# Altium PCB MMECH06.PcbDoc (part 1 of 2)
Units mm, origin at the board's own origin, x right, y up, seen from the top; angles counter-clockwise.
Board outline 65 x 56.01 mm, 4 copper layers (Top Layer, Ground Plane, Mid Layer 1, Bottom Layer), stack 1.442 mm thick; 107 components, 79 nets, 362 pads, 608 vias.
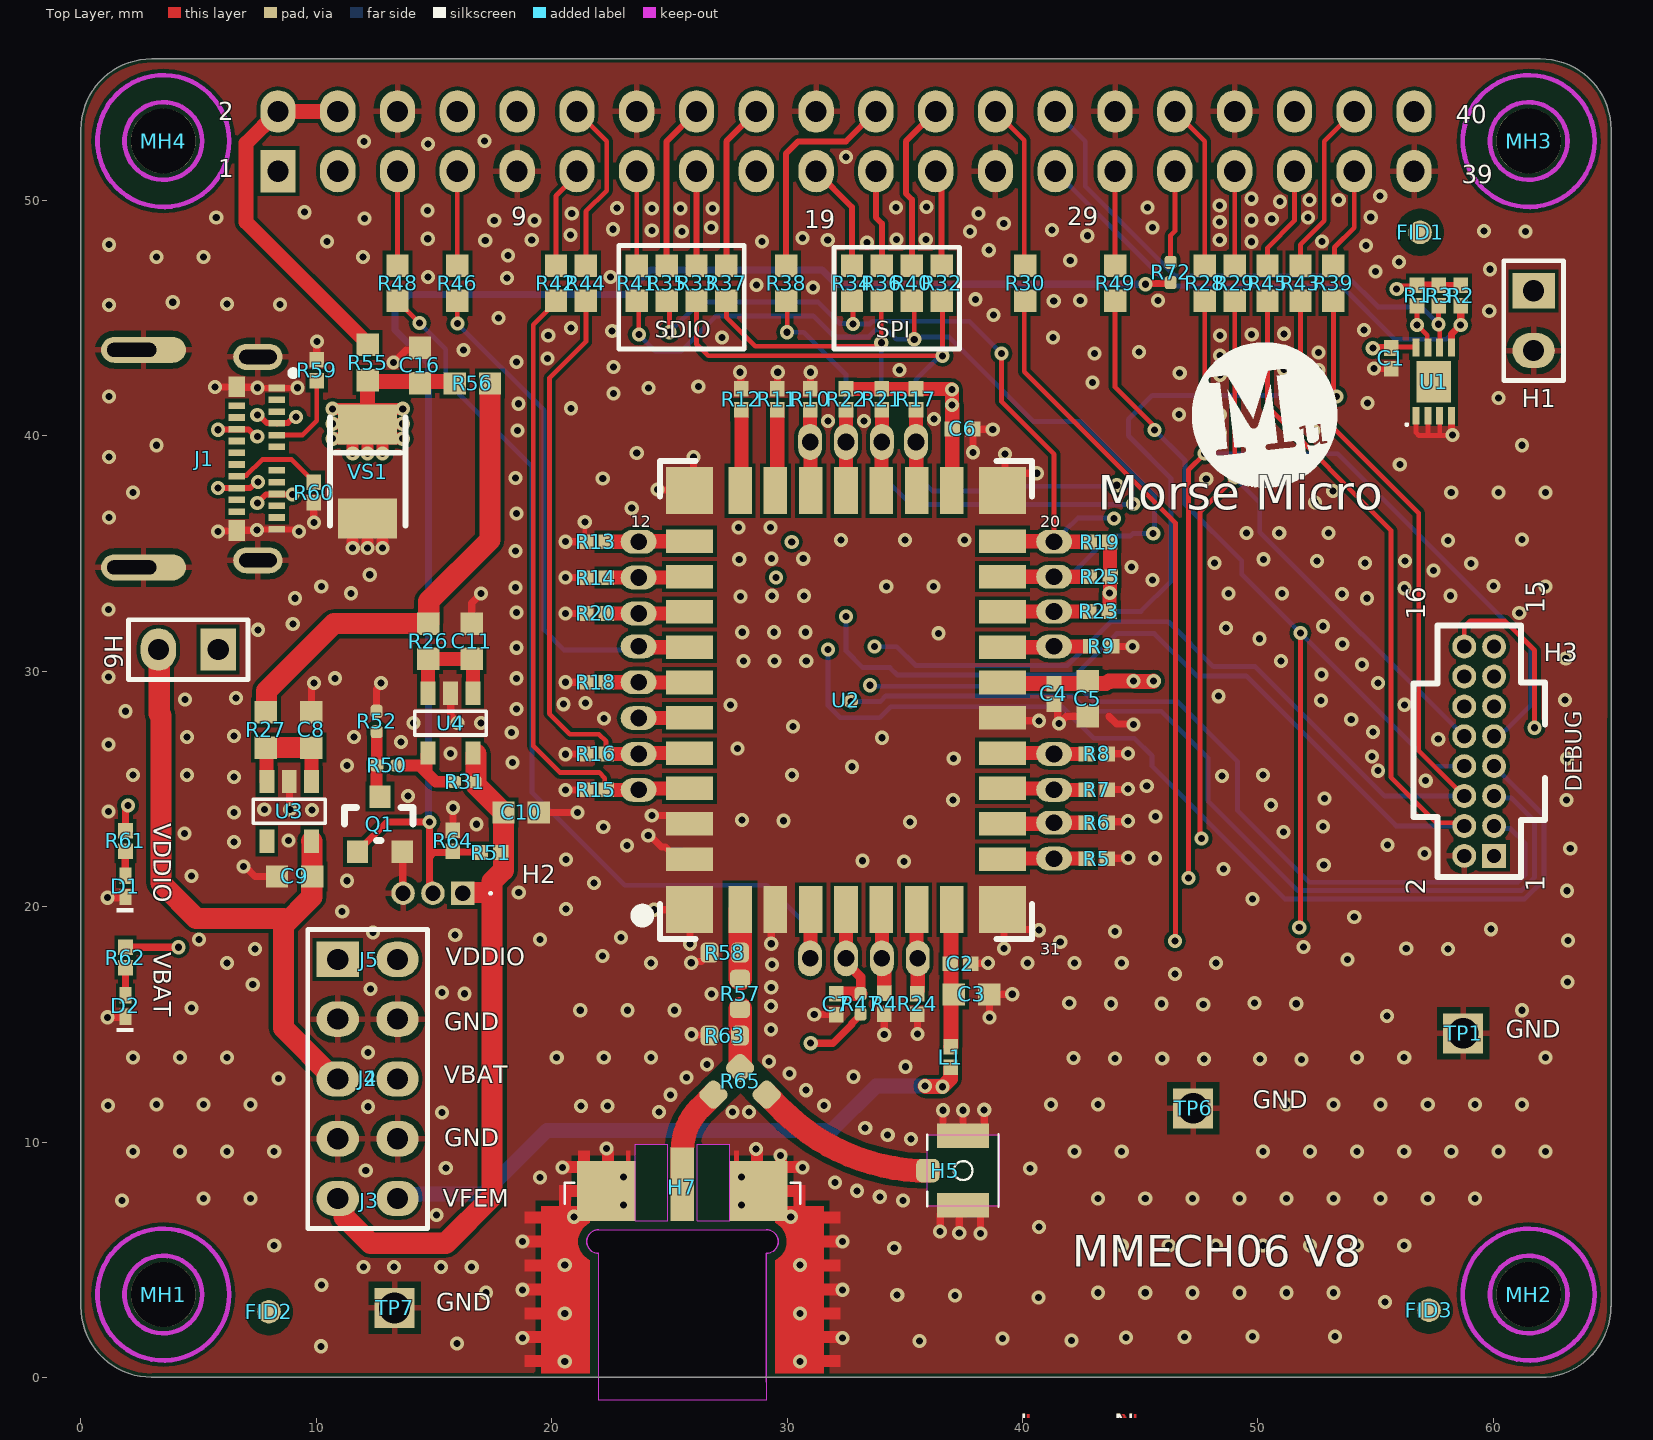
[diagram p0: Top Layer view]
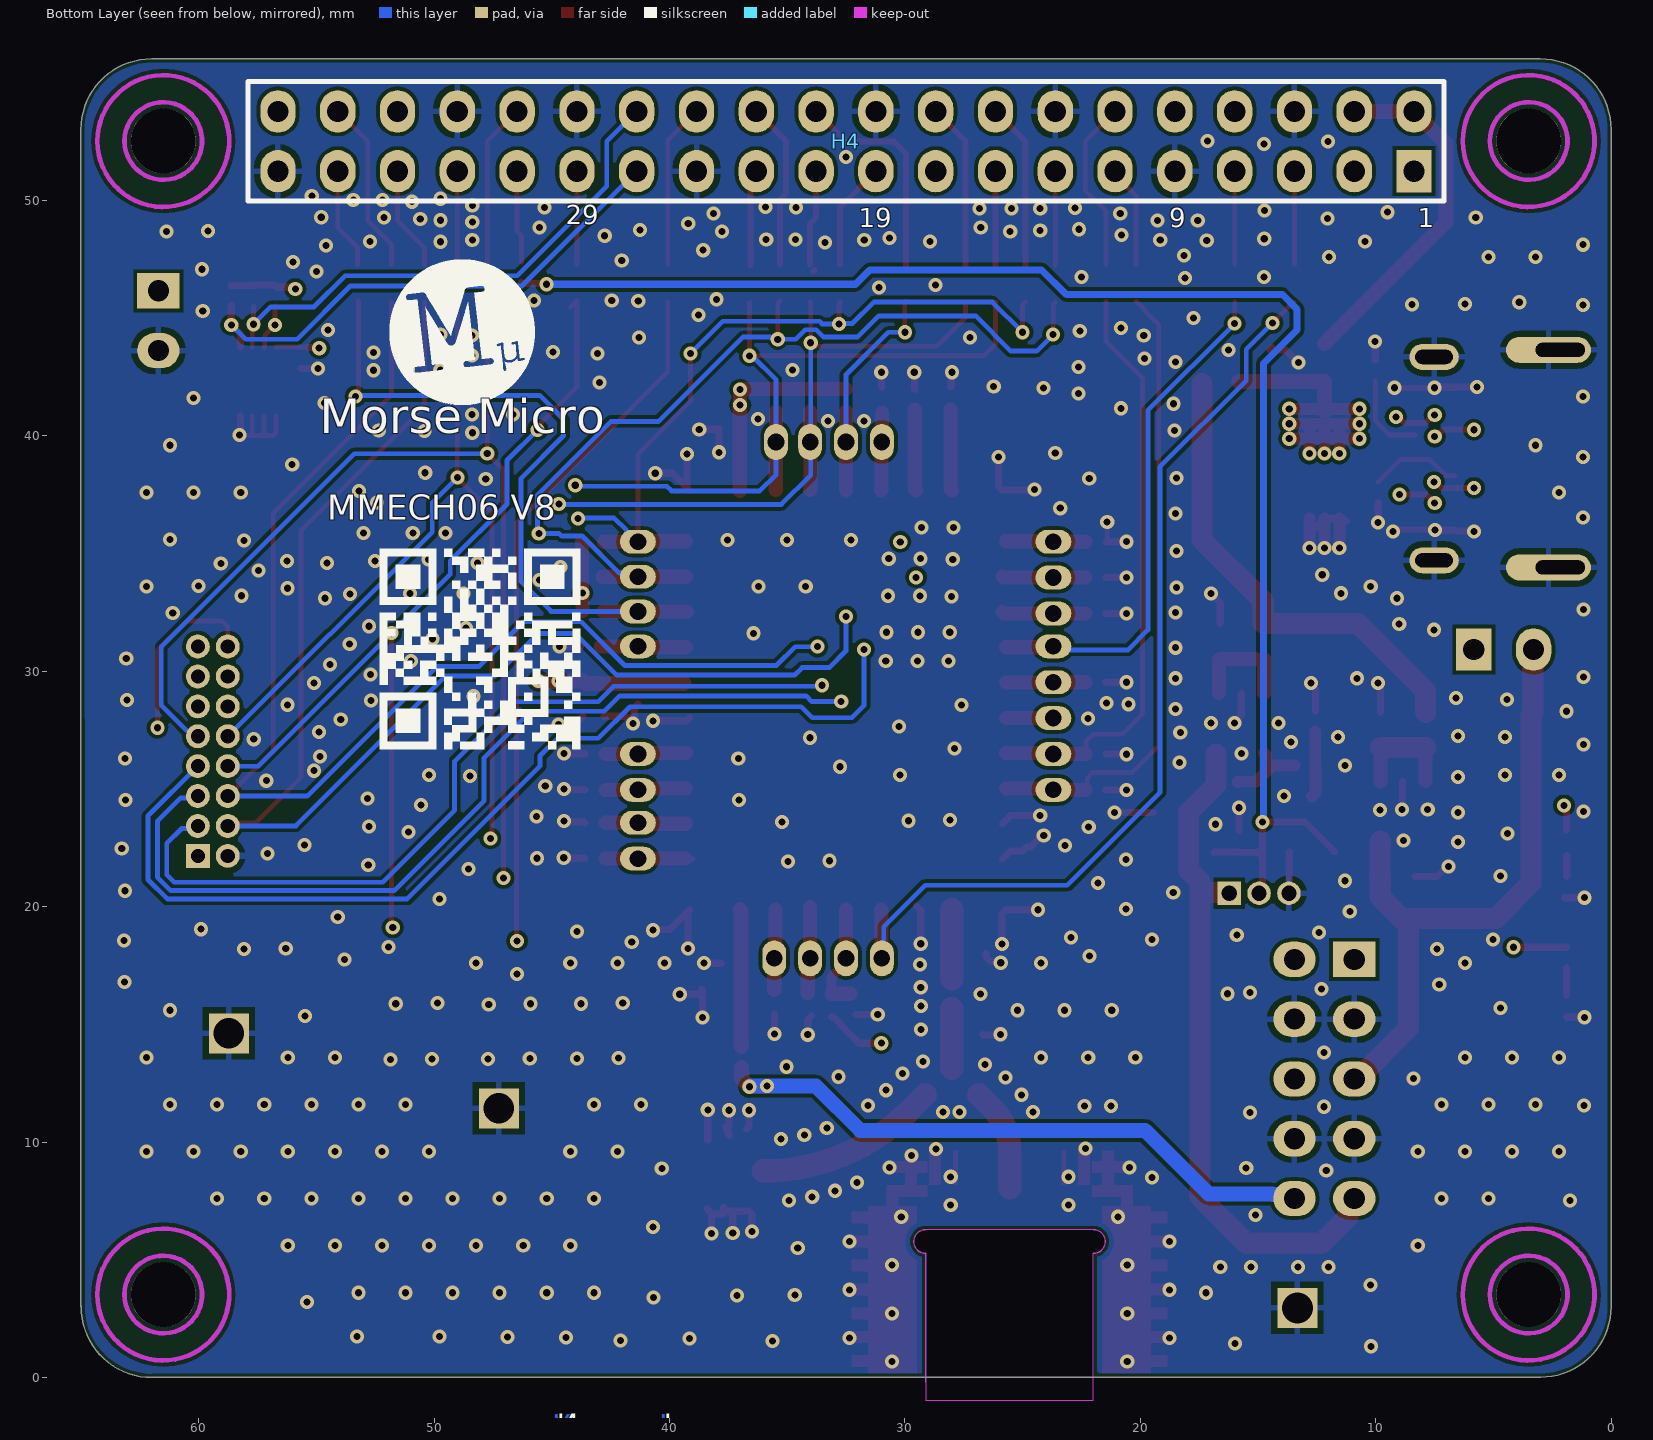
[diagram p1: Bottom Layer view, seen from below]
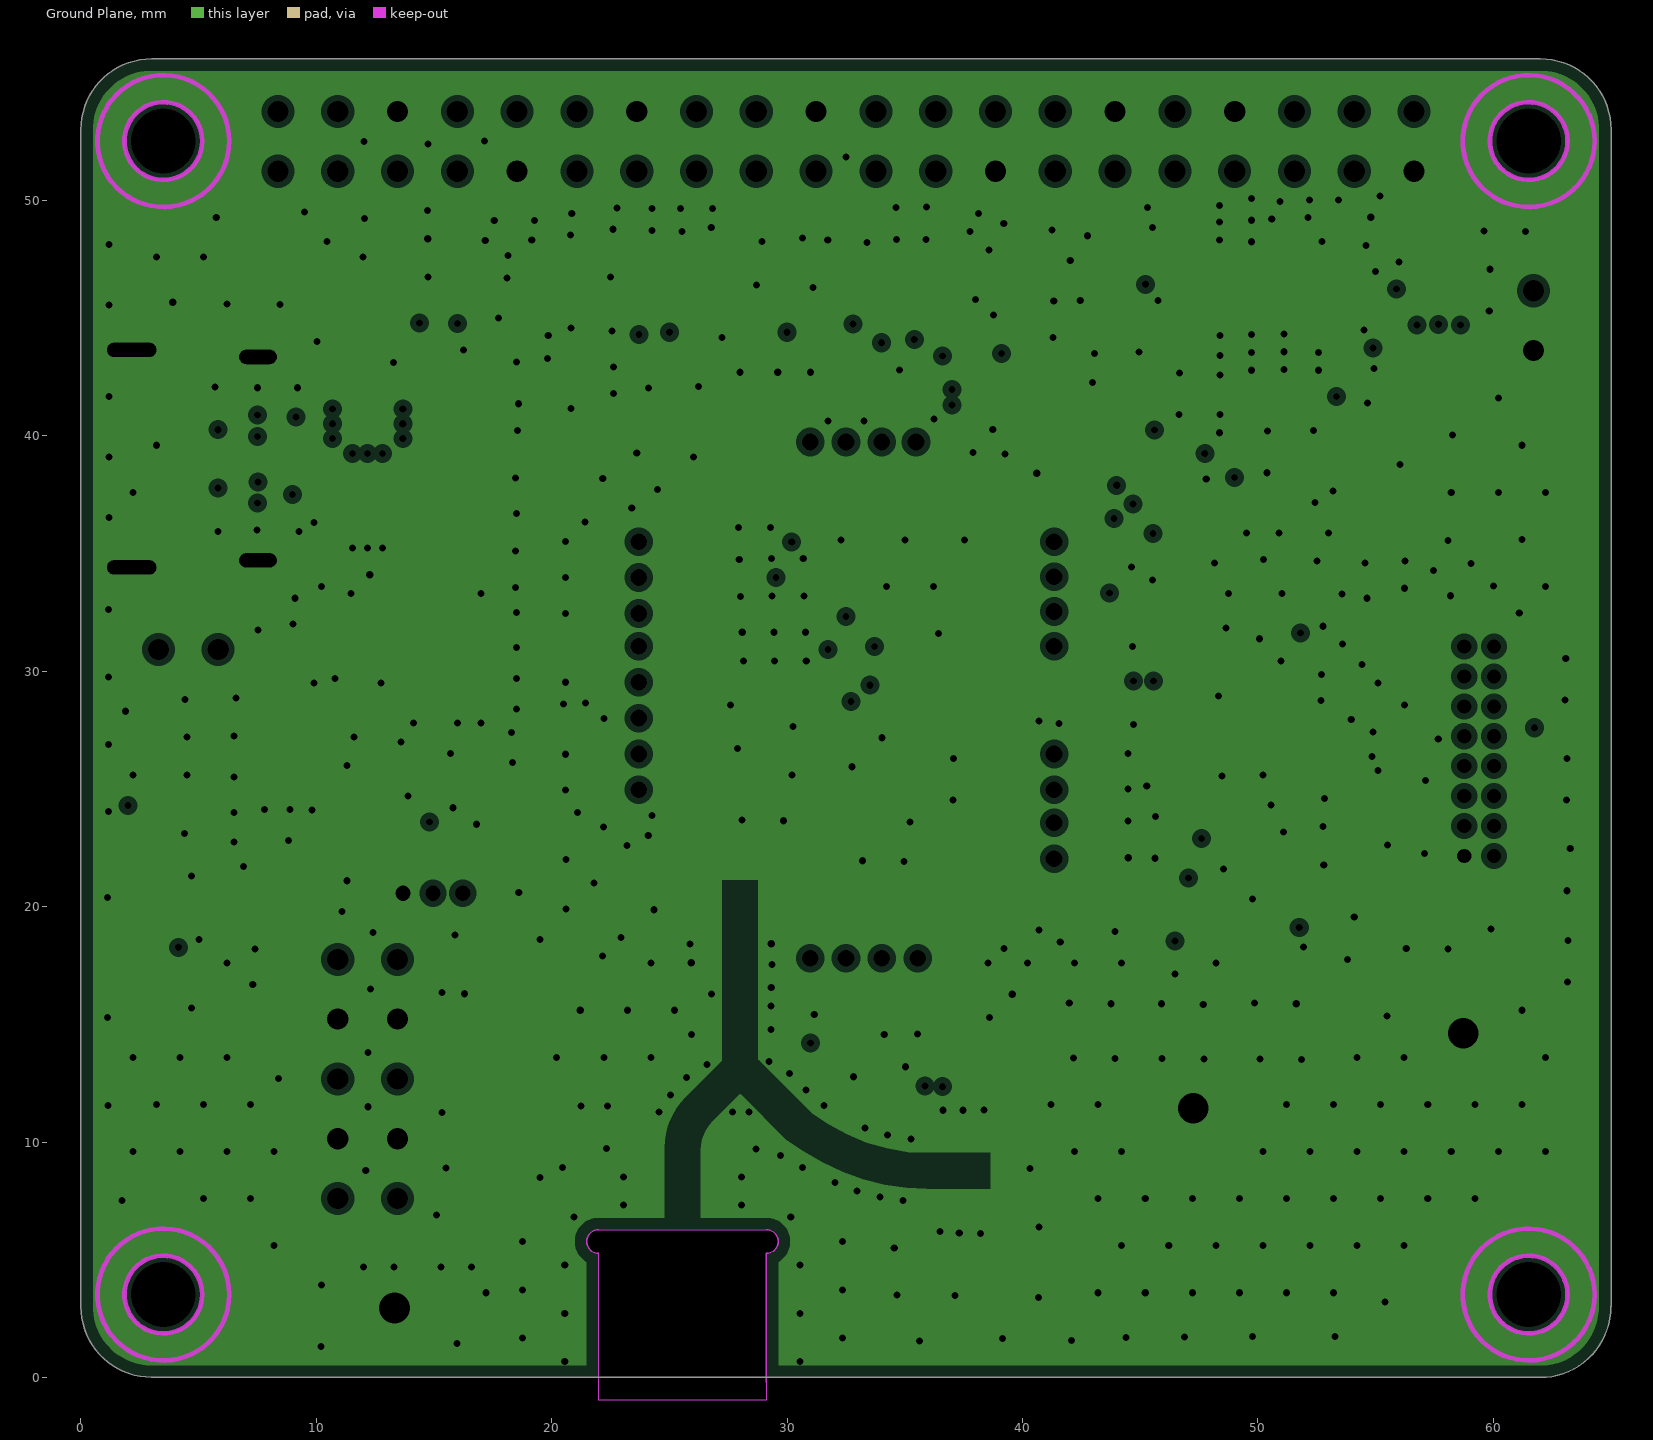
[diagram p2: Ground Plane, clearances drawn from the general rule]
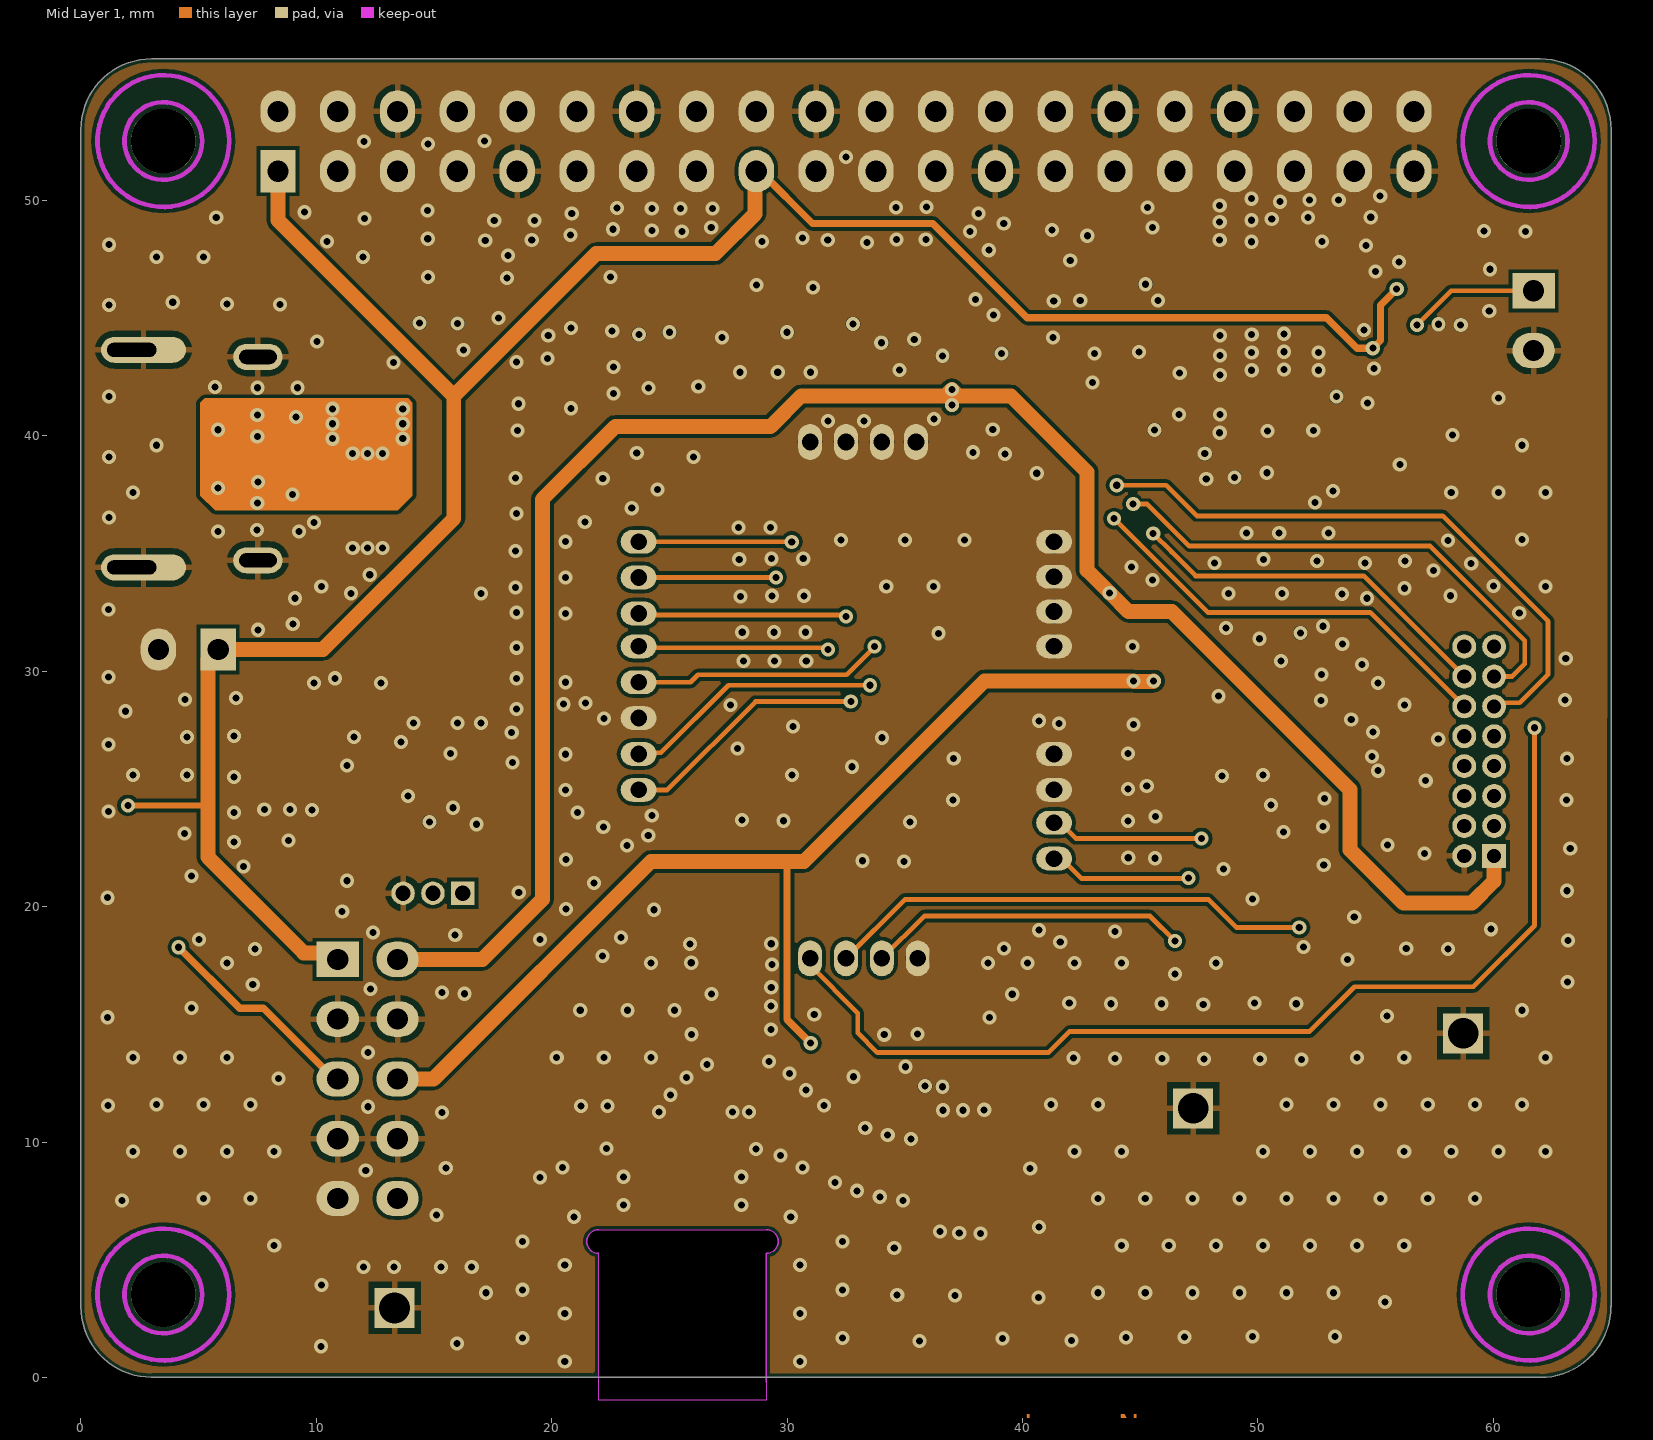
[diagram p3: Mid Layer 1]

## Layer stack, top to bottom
Top Solder: solder mask 0.02, SM-001, Dk 4.2
Top Layer: signal copper 0.035
Dielectric 1: prepreg 0.3048, PP, Dk 4.29
Ground Plane: plane copper 0.035, net GND
Dielectric 2: core 0.692, Core, Dk 4.29
Mid Layer 1: signal copper 0.035
Dielectric 3: prepreg 0.3048, PP, Dk 4.29
Bottom Layer: signal copper 0.035
Bottom Solder: solder mask 0.02, SM-001, Dk 4.2

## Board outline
0,3.011 0,53.011 cw(c3,53.011) 3,56.011 62,56.011 cw(c62,53.011) 65,53.011 65,3.011 64.988,3 cw(c61.988,3) 61.988,0 3.011,0 3,0.011 cw(c3,3.011)

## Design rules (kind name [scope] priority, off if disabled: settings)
AssemblyTestPointUsage [All] p1 off:
AssemblyTestpoint [All] p1 off: testpointundercomponent=TRUE minsize=1.016 maxsize=2.54 preferedsize=1.524 minholesize=0 maxholesize=1.016 preferedholesize=0.813 testpointgrid=0.025 usegrid=TRUE gridtolerance=0 allowsidetop=TRUE allowsidebottom=TRUE
BoardOutlineClearance [(not OnTopSilkscreen) AND (NOT OnBottomSilkscreen) and (not OnMultiLayer)] p1: gap=0.152 ignorepadtopadclearanceinfootprint=FALSE
Clearance "Schematic Clearance Constraint_2" [InComponent('FID3')] p1: gap=0 ignorepadtopadclearanceinfootprint=FALSE
Clearance "Schematic Clearance Constraint_1" [InComponent('FID2')] p2: gap=0 ignorepadtopadclearanceinfootprint=FALSE
Clearance "Schematic Clearance Constraint" [InComponent('FID1')] p3: gap=0 ignorepadtopadclearanceinfootprint=FALSE
Clearance Clearance_RF_Poly [(InPolygon) vs InNetClass('RF-Net')] p4: gap=0.255 ignorepadtopadclearanceinfootprint=TRUE
Clearance Clearance_RF [InNetClass('RF-Net')] p5: gap=0.254 ignorepadtopadclearanceinfootprint=TRUE
Clearance [All] p6: gap=0.152 ignorepadtopadclearanceinfootprint=TRUE
ComponentClearance [All] p1 off: gap=0.254 collisioncheckmode=3 verticalgap=0.254 showdistances=FALSE
DiffPairsRouting [All] p1 off: maxlimit=0.254 minlimit=0.254 mostfreqgap=0.254 toplayer_minwidth=0.381 toplayer_maxwidth=0.381 toplayer_prefwidth=0.381 midlayer3_minwidth=0.381 midlayer3_maxwidth=0.381 midlayer3_prefwidth=0.381 bottomlayer_minwidth=0.381 bottomlayer_maxwidth=0.381 bottomlayer_prefwidth=0.381 maxuncoupledlength=12.7
FabricationTestPointUsage [All] p1 off: valid=0 allowmultiple=FALSE
FabricationTestpoint [All] p1 off: side=3 testpointundercomponent=TRUE minsize=1.016 maxsize=2.54 preferedsize=1.524 minholesize=0 maxholesize=1.016 preferedholesize=0.813 testpointgrid=0.025 allowsidetop=TRUE allowsidebottom=TRUE usegrid=TRUE gridtolerance=0
FanoutControl Fanout_BGA [IsBGA] p1 off: bgadir=Out bgaviamode=Centered fanoutstyle=Auto fanoutdirection=Alternating viagrid=0.025 // Fanout_BGA (Default Rule)
FanoutControl Fanout_LCC [IsLCC] p2 off: bgadir=Out bgaviamode=Centered fanoutstyle=Auto fanoutdirection=Alternating viagrid=0.025 // Fanout_LCC (Default Rule)
FanoutControl Fanout_SOIC [IsSOIC] p3 off: bgadir=Out bgaviamode=Centered fanoutstyle=Auto fanoutdirection=Alternating viagrid=0.025 // Fanout_SOIC (Default Rule)
FanoutControl Fanout_Small [(CompPinCount < 5)] p4 off: bgadir=Out bgaviamode=Centered fanoutstyle=Auto fanoutdirection=OutThenIn viagrid=0.025 // Fanout_Small (Default Rule)
FanoutControl Fanout_Default [All] p5 off: bgadir=Out bgaviamode=Centered fanoutstyle=Auto fanoutdirection=Alternating viagrid=0.025 // Fanout_Default (Default Rule)
Height TP1 [InComponent('TP1')] p1: minheight=0 maxheight=12 prefheight=3
Height "POGO Pins" [InComponentClass('POGO')] p2: minheight=0 maxheight=7 prefheight=5
Height "Under Socket" [WithinRoom('ROOM_SOCKET')] p3: minheight=0 maxheight=4 prefheight=3
Height [All] p4 off: minheight=0 maxheight=25.4 prefheight=12.7
HoleSize [All] p1: absolutevalues=TRUE maxlimit=5.08 minlimit=0.203 maxpercent=80.000 minpercent=20.000
HoleToHoleClearance [All] p1: gap=0.203 allowstackedmicrovias=TRUE
LayerPairs [All] p1 off: enforce=TRUE
MatchedLengths MatchLengths_U1_Passives_J5_1 [InxSignalClass('xSignals_U1_Passives_J5_MatchLengthsClass_1')] p1: tolerance=1.27 checknetsindiffpair=FALSE checkdiffpairvsdiffpair=TRUE checkxsignals=TRUE checkothers=TRUE
MatchedLengths MatchLengths_U1_Passives_J5 [InxSignalClass('xSignals_U1_Passives_J5_MatchLengthsClass')] p2: tolerance=1.27 checknetsindiffpair=FALSE checkdiffpairvsdiffpair=TRUE checkxsignals=TRUE checkothers=TRUE
MinimumSolderMaskSliver [not InComponent('U4','U1','U5','U6','U7','U8','U9','U10','H2','H3')] p1: minsoldermaskwidth=0.076
PlaneClearance [All] p1: clearance=0.254
PlaneConnect PlaneConnect_1 [(InComponent('J5') OR InComponent('J6') OR InComponent('J13') OR InComponent('J11') OR InComponent('J12'))] p1: planeconnectstyle=Relief reliefexpansion=0.4 reliefentries=4 reliefconductorwidth=0.254 reliefairgap=0.2
PlaneConnect [All] p2: pad.planeconnectstyle=Relief pad.reliefexpansion=0.508 pad.reliefentries=4 pad.reliefconductorwidth=0.254 pad.reliefairgap=0.254 via.planeconnectstyle=Direct via.reliefexpansion=0.508 via.reliefentries=4 via.reliefconductorwidth=0.254 via.reliefairgap=0.254
PolygonConnect PolygonConnect_1 [InNet('GND') vs (InComponent('J5') OR InComponent('J6') OR InComponent('J13') OR InComponent('J11') OR InComponent('J12'))] p1: connectstyle=Relief reliefconductorwidth=0.254 reliefentries=4 polygonreliefangle="90 Angle" airgapwidth=0.2
PolygonConnect [All] p2: thpad.connectstyle=Relief thpad.reliefconductorwidth=0.254 thpad.reliefentries=4 thpad.polygonreliefangle="90 Angle" thpad.airgapwidth=0.254 smdpad.connectstyle=Direct smdpad.reliefconductorwidth=0.254 smdpad.reliefentries=4 smdpad.polygonreliefangle="90 Angle" smdpad.airgapwidth=0.254 via.connectstyle=Direct via.reliefconductorwidth=0.254 via.reliefentries=4 via.polygonreliefangle="90 Angle" via.airgapwidth=0.254
RoutingVias [All] p1: holewidth=0.3 width=0.6 viastyle="Through Hole" minholewidth=0.203 minwidth=0.5 maxholewidth=0.711 maxwidth=1.27
SilkToSilkClearance [All] p1 off: silktosilkclearance=0.203
SilkToSolderMaskClearance [IsPad] p1 off: minsilkscreentomaskgap=0.102 clearancetoexposedcopper=TRUE
SolderMaskExpansion [All] p1: expansion=0.102 istentingtop=FALSE
SupplyNets SupplyNets_1 [InNet('VDD33')] p1: voltage=3.300
SupplyNets SupplyNets_2 [InNet('VBAT')] p2: voltage=3.300
SupplyNets SupplyNets_3 [InNet('VDD5')] p3: voltage=5.000
SupplyNets SupplyNets_4 [InNet('VDD5_RPi')] p4: voltage=5.000
SupplyNets SupplyNets_5 [InNet('VDD_FEM')] p5: voltage=4.000
SupplyNets SupplyNets_6 [InNet('VDD_LNA')] p6: voltage=4.000
SupplyNets SupplyNets_7 [InNet('VDD_PA')] p7: voltage=4.000
SupplyNets [InNet('GND')] p8: voltage=0.000
UnConnectedPin [All] p1 off:
UnRoutedNet [All] p1: checkbadconnections=TRUE
Width "RF Width" [InNetClass('RF-Net')] p1: maxlimit=1 minlimit=0.178 preferedwidth=0.254 toplayer_minwidth=1 toplayer_prefwidth=1 impedanceprofiledriven=TRUE impedanceprofileid={FB8584CB-3844-47FA-94E5-229847F5405A} impedanceprofilevalue=50.000000 minimp=50.000000 maximp=50.000000 favimp=50.000000
Width [All] p2: maxlimit=1.27 minlimit=0.203 preferedwidth=0.203
9 further rules are at their usual default settings.

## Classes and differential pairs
net class RF-Net: NetH5_1 NetH7_1 NetR57_1 NetR57_2
component class CHIP_OTHER: C3 C5 C8 C9 C10 C11 C16 D1 D2 R26 R27 R28 R29 R30 R32 R33 R34 R35 R36 R37 R38 R39 R40 R41 R42 R43 R44 R45 R46 R48 R49 R55 R56 R57 R58 R63 R65
component class MMECH06_Power: C8 C9 C10 C11 C16 D1 D2 FID1 FID2 FID3 H2 H6 J1 J2 J3 J4 J5 MH1 MH2 MH3 MH4 Q1 R26 R27 R31 R50 R51 R52 R55 R56 R59 R60 R61 R62 R64 R72 TP1 TP6 TP7 U3 U4 VS1
component class CHIP_MICRO: C1 C2 C4 C6 C7 L1 R1 R2 R3 R4 R5 R6 R7 R8 R9 R10 R11 R12 R13 R14 R15 R16 R17 R18 R19 R20 R21 R22 R23 R24 R25 R31 R47 R50 R51 R52 R59 R60 R61 R62 R64 R72
component class MMECH06_Module: C1 C2 C3 C4 C5 C6 C7 H1 H3 H4 H5 H7 L1 R1 R2 R3 R4 R5 R6 R7 R8 R9 R10 R11 R12 R13 R14 R15 R16 R17 R18 R19 R20 R21 R22 R23 R24 R25 R28 R29 R30 R32 R33 R34 R35 R36 R37 R38 R39 R40 R41 R42 R43 R44 R45 R46 R47 R48 R49 R57 R58 R63 R65 U1 U2
component class PCB_PATTERN: FID1 FID2 FID3 FID7 FID8 MH1 MH2 MH3 MH4
component class COMP_OTHER: H1 H2 H3 H4 H5 H6 J1 J2 J3 J4 J5 Q1 TP1 TP6 TP7 U1 U2 U3 U4 VS1

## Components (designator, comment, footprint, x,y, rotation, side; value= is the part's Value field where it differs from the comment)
C1 "CAP" CAPC1005X06N 55.665,43.291 r270 top value=100nF
C2 "CAP" CAPC1005X06N 37.36,17.58 r0 top value=100nF
C3 "CAP" CAPC1608X06N 37.834,16.271 r0 top value=10uF
C4 "CAP" CAPC1005X06N 41.334,29.038 r90 top value=100nF
C5 "CAP" CAPC1608X06N 42.766,28.838 r270 top value=10uF
C6 "CAP" CAPC1005X06N 37.453,40.29 r0 top value=100nF
C7 "CAP" CAPC1005X06N 32.094,15.855 r270 top value=2.2uF
C8 "CAP" CAPC1608X06N 9.79,27.504 r270 top value=10uF
C9 "CAP" CAPC1608X06N 9.079,21.281 r0 top value=10uF
C10 "CAP" CAPC1608X06N 18.7,24 r180 top value=10uF
C11 "CAP" CAPC1608X06N 16.6,31.275 r270 top value=10uF
C16 "CAP" CAPC1608X06N 14.402,42.988 r90 top value=10uF
D1 "LED_G" LED_0402_GREEN 1.893,20.86 r270 top value=Green
D2 "LED_G" LED_0402_GREEN 1.893,15.78 r270 top value=Green
FID1 "FIDUCIAL" FIDUCIAL_1MM 56.884,48.641 r0 top
FID2 "FIDUCIAL" FIDUCIAL_1MM 7.989,2.794 r0 top
FID3 "FIDUCIAL" FIDUCIAL_1MM 57.265,2.854 r90 top
H1 "HDR_1X2_DNF" HDR1X2_DNF 61.71,46.161 r270 top
H2 "HDR_1X3" HPH1A03UA 16.223,20.567 r180 top
H3 "2X8_FTSH_DV_K" FTSH_108_D_K 59.399,26.603 r90 top
H4 "HDR_2X20" HDR2X20F 8.37,51.241 r0 bottom locked
H5 "U_FL-R-SMT" U_FL-R-SMT 37.476,8.789 r270 top
H6 "HDR_1X2" HDR1X2 5.83,30.921 r180 top
H7 "SM2924" SM2924-Footprint-1 25.552,0.925 r90 top
J1 "CONN RCP USB3.1 TYPEC 24P SMD RA" USB-C_RCP 5.244,39.03 r270 top
J2 "HDR_2X5" HDR2X5 10.91,17.761 r270 top
J3 "QPC02SXGN-RC" QPC02SXGN-RC 12.25,7.5 r0 top
J4 "QPC02SXGN-RC" QPC02SXGN-RC 12.195,12.705 r0 top
J5 "QPC02SXGN-RC" QPC02SXGN-RC 12.25,17.75 r0 top
L1 "IND" INDC1005X06N 36.946,13.613 r270 top value="60 Ohms @ 100MHz"
MH1 "MH_300_275_NPTH" MH_300_275_NPTH 3.5,3.522 r0 top
MH2 "MH_300_275_NPTH" MH_300_275_NPTH 61.5,3.522 r0 top
MH3 "MH_300_275_NPTH" MH_300_275_NPTH 61.5,52.522 r0 top
MH4 "MH_300_275_NPTH" MH_300_275_NPTH 3.5,52.522 r0 top
Q1 "MOSFET_NCH_LGD" SOT-23 12.7,23.5 r0 top value=BSS138K
R1 "RES" RESC1005X04N 56.757,45.966 r270 top value=1K
R2 "RES" RESC1005X04N 58.611,45.958 r270 top value=3k9
R3 "RES" RESC1005X04N 57.671,45.958 r270 top value=3k9
R4 "RES" RESC1005X04N 34.124,15.876 r270 top value=10K
R5 "RES" RESC1005X04N 43.157,22.04 r0 top value=10K
R6 "RES" RESC1005X04N 43.157,23.564 r0 top value=10K
R7 "RES" RESC1005X04N 43.157,24.961 r0 top value=10K
R8 "RES" RESC1005X04N 43.157,26.485 r0 top value=10K
R9 "RES" RESC1005X04N 43.341,31.057 r0 top value=10K
R10 "RES" RESC1005X04N 30.976,41.55 r90 top value=10K
R11 "RES" RESC1005X04N 29.579,41.55 r90 top value=10K
R12 "RES" RESC1005X04N 28.055,41.55 r90 top value=10K
R13 "RES" RESC1005X04N 21.879,35.502 r180 top value=10K
R14 "RES" RESC1005X04N 21.879,33.978 r180 top value=10K
R15 "RES" RESC1005X04N 21.879,24.961 r180 top value=10K
R16 "RES" RESC1005X04N 21.879,26.485 r180 top value=10K
R17 "RES" RESC1005X04N 35.473,41.55 r270 top value=47k
R18 "RES" RESC1005X04N 21.879,29.533 r180 top value=10K
R19 "RES" RESC1005X04N 43.27,35.49 r180 top value=47k
R20 "RES" RESC1005X04N 21.879,32.454 r180 top value=10K
R21 "RES" RESC1005X04N 34.024,41.55 r90 top value=47k
R22 "RES" RESC1005X04N 32.5,41.55 r90 top value=47k
R23 "RES" RESC1005X04N 43.246,32.539 r0 top value=47k
R24 "RES" RESC1005X04N 35.533,15.868 r270 top value=10K
R25 "RES" RESC1005X04N 43.276,34.013 r180 top value=47k
R26 "RES" RESC1608X06N 14.747,31.275 r90 top value=0R
R27 "RES" RESC1608X06N 7.859,27.504 r90 top value=0R
R28 "RES" RESC1608X06N 47.74,46.482 r90 top value=0R
R29 "RES" RESC1608X06N 49.01,46.482 r90 top value=0R
R30 "RES" RESC1608X06N 40.12,46.482 r90 top value=0R
R31 "RES" 0402_res_rnd 16.3,25.3 r180 top value=82k
R32 "RES_DNF" RESC1608X06N_DNF 36.564,46.482 r270 top value=DNF
R33 "RES" RESC1608X06N 26.15,46.482 r90 top value=47R
R34 "RES_DNF" RESC1608X06N_DNF 32.754,46.482 r270 top value=DNF
R35 "RES" RESC1608X06N 24.88,46.482 r90 top value=47R
R36 "RES_DNF" RESC1608X06N_DNF 34.024,46.482 r270 top value=DNF
R37 "RES" RESC1608X06N 27.42,46.482 r90 top value=47R
R38 "RES" RESC1608X06N 29.96,46.482 r90 top value=47R
R39 "RES" RESC1608X06N 53.204,46.482 r90 top value=47R
R40 "RES_DNF" RESC1608X06N_DNF 35.294,46.482 r270 top value=DNF
R41 "RES" RESC1608X06N 23.61,46.482 r90 top value=47R
R42 "RES" RESC1608X06N 20.181,46.482 r90 top value=0R
R43 "RES" RESC1608X06N 51.804,46.482 r90 top value=0R
R44 "RES" RESC1608X06N 21.451,46.482 r90 top value=0R
R45 "RES" RESC1608X06N 50.407,46.482 r90 top value=0R
R46 "RES" RESC1608X06N 15.99,46.482 r90 top value=0R
R47 "RES" 0402_res_rnd 33.12,15.868 r90 top value=100k
R48 "RES" RESC1608X06N 13.45,46.482 r90 top value=10k
R49 "RES" RESC1608X06N 43.93,46.482 r90 top value=0R
R50 "RES" 0402_res_rnd 13,26 r180 top value=18.7k
R51 "RES" RESC1005X04N 17.4,22.3 r180 top value=10k
R52 "RES" 0402_res_rnd 12.562,27.867 r90 top value=7.32k
R55 "RES" RESC1608X06N 12.18,43.113 r270 top value=0R
R56 "RES" RESC1608X06N 16.625,42.224 r0 top value=0R
R57 "RES" RESC1608X06L 28,16.296 r270 top value=0R
R58 "RES" RESC1608X06L 27.35,18.046 r0 top value=0R
R59 "RES" RESC1005X04N 10.021,42.783 r90 top value=5K1
R60 "RES" RESC1005X04N 9.894,37.592 r270 top value=5K1
R61 "RES" RESC1005X04N 1.893,22.793 r90 top value=330R
R62 "RES" RESC1005X04N 1.893,17.84 r90 top value=330R
R63 "RES" RESC1608X06L 27.35,14.521 r180 top value=0R
R64 "RES" RESC1005X04N 15.8,22.8 r90 top value=10k
R65 "RES_AC" 0603_RES_AC_RA 27.434,12.58 r225 top value=0R
R72 "RES" 0402_res_rnd 46.29,46.938 r90 top value=1k
TP1 "TP-BLK" TP-100_BLACK 58.713,14.614 r0 top
TP6 "TP-BLK" TP-100_BLACK 47.244,11.43 r0 top
TP7 "TP-BLK" TP-100_BLACK 13.323,2.953 r0 top
U1 "CAT24C32HU4I-GT3" DFN8 57.468,42.3 r90 top
U2 "MM6108-MF08651-US" MF04 32.5,28.771 r90 top locked value=MM61xx-MF08251
U3 "LDO_REG2_EN" SOT-23_5 8.85,24.05 r270 top value=RT9080-33GJ5
U4 "RT9187C" SOT-23_5 15.7,27.8 r270 top value=RT9187CGB
VS1 "Varistor_Uni" DO-214AC 12.18,38.481 r90 top value=6V

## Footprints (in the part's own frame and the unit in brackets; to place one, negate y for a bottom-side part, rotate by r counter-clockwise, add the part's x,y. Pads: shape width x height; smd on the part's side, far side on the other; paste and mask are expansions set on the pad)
0402_res_rnd [mil]
  rrect50% 22x20 smd: 1(-17,0) 2(17,0)
  body extent -21,-11 21,11, height 16
0603_RES_AC_RA [mm]
  rrect50% 1x1 smd: A(-0.8,0) B(0.8,0) C(-0.8,1.6)
  body extent -1.27,-0.02 -0.32,1.63, height 0.55
CAPC1005X06N [mm] "Chip Capacitor, 2-Leads, Body 1.00x0.50mm, IPC Medium Density"
  rect 0.66x0.62 smd: 1(-0.44,0) 2(0.44,0)
  body extent -0.53,-0.28 0.52,0.28, height 0.55
CAPC1608X06N [mm] "Chip Capacitor, 2-Leads, Body 1.60x0.80mm, IPC Medium Density"
  rect 0.95x0.95 smd: 1(-0.75,0) 2(0.75,0)
  body extent -0.82,-0.45 0.82,0.45, height 0.6
DFN8 [mm] "8DFN 8-Leads, Body 3.00x2.00mm, Pitch 0.50mm"
  rect 0.75x0.3 smd paste+0 mask+0.051: 1(-1.45,0.75) 2(-1.45,0.25) 3(-1.45,-0.25) 4(-1.45,-0.75) 5(1.45,-0.75) 6(1.45,-0.25) 7(1.45,0.25) 8(1.45,0.75)
  rect 1.75x1.45 smd paste+0 mask+0: 9(0,0)
  silkscreen extent -1.87,1.1 -1.78,1.2, body extent -1.5,-1 1.5,1, height 0.94
DO-214AC [mm]
  rect 1.7x2.5 smd: A(-2,0) K(2,0)
  silkscreen extent -2.3,-1.6 2.3,1.6, body extent -2.6,-1.4 2.6,1.4, height 2.3
FIDUCIAL_1MM [mm]
  round 1 smd paste-1 mask+0.5: 1(0,0)
  Top Layer pour cut-out: -1,0 -0.924,-0.383 -0.707,-0.707 -0.383,-0.924 0,-1 0,-1 0.383,-0.924 0.707,-0.707 0.924,-0.383 1,0 1,0 0.924,0.383 0.707,0.707 0.383,0.924 0,1 0,1 -0.383,0.924 -0.707,0.707 -0.924,0.383 -1,0
FTSH_108_D_K [mil]
  rect 40x40 hole 23.62: 1(-175,-25)
  round 40 hole 23.62: 2(-175,25) 3(-125,-25) 4(-125,25) 5(-75,-25) 6(-75,25) 7(-25,-25) 8(-25,25) 9(25,-25) 10(25,25) 11(75,-25) 12(75,25) 13(125,-25) 14(125,25) 15(175,-25) 16(175,25)
  silkscreen extent -210,-110 210,110, body extent -200,-100 200,100, height 225
HDR1X2 [mm] "Connector; Header; 2 Position"
  rect 1.5x1.8 hole 0.9: 1(0,0)
  oval 1.5x1.8 hole 0.9: 2(2.54,0)
  silkscreen extent -1.27,-1.27 3.81,1.27, body extent -1.27,-1.22 3.81,1.22, height 10.3
HDR1X2_DNF [mm] "Connector; Header; 2 Position"
  rect 1.5x1.8 hole 0.9: 1(0,0)
  oval 1.5x1.8 hole 0.9: 2(2.54,0)
  silkscreen extent -1.27,-1.27 3.81,1.27, body extent -1.27,-1.27 3.81,1.27, height 0.01
HDR2X5 [mm] "Connector; Header; 5x2 Position"
  rect 1.5x1.8 hole 0.9: 1(0,0)
  oval 1.5x1.8 hole 0.9: 2(0,2.54) 3(2.54,0) 4(2.54,2.54) 5(5.08,0) 6(5.08,2.54) 7(7.62,0) 8(7.62,2.54) 9(10.16,0) 10(10.16,2.54)
  silkscreen extent -1.27,-1.27 11.43,3.81, body extent -1.27,-1.27 11.43,3.81, height 9
HDR2X20F [mm] "Connector; Header; 20x2 Position Female"
  rect 1.5x1.8 hole 0.9: 1(0,0)
  oval 1.5x1.8 hole 0.9: 2(0,-2.54) 3(2.54,0) 4(2.54,-2.54) 5(5.08,0) 6(5.08,-2.54) 7(7.62,0) 8(7.62,-2.54) 9(10.16,0) 10(10.16,-2.54) 11(12.7,0) 12(12.7,-2.54) 13(15.24,0) 14(15.24,-2.54) 15(17.78,0) 16(17.78,-2.54) 17(20.32,0) 18(20.32,-2.54) 19(22.86,0) 20(22.86,-2.54) 21(25.4,0) 22(25.4,-2.54) 23(27.94,0) 24(27.94,-2.54) 25(30.48,0) 26(30.48,-2.54) 27(33.02,0) 28(33.02,-2.54) 29(35.56,0) 30(35.56,-2.54) 31(38.1,0) 32(38.1,-2.54) 33(40.64,0) 34(40.64,-2.54) 35(43.18,0) 36(43.18,-2.54) 37(45.72,0) 38(45.72,-2.54) 39(48.26,0) 40(48.26,-2.54)
  silkscreen extent -1.27,-3.81 49.53,1.27, body extent -1.27,-3.81 49.53,1.27, height 8
HPH1A03UA [mm]
  rect 1x1 hole 0.65: 1(0,0)
  round 1 hole 0.65: 2(1.27,0) 3(2.54,0)
  silkscreen extent -1.23,-0.05 -1.13,0.05, body extent -0.64,-0.9 3.17,0.9, height 4.08
INDC1005X06N [mm] "Chip Inductor, 2-Leads, Body 1.00x0.50mm, IPC Medium Density"
  rect 0.66x0.62 smd: 1(-0.44,0) 2(0.44,0)
  body extent -0.53,-0.28 0.53,0.28, height 0.55
LED_0402_GREEN [mm]
  rect 0.7x0.5 smd: A(-0.45,0) K(0.45,0)
  silkscreen extent 0.92,-0.37 1.1,0.35, body extent -0.5,-0.25 0.5,0.25, height 0.51
MF04 [mm]
  rect 2x2 smd: 1(-8.9,6.65) 12(8.9,6.65) 20(8.9,-6.65) 31(-8.9,-6.65)
  rect 1x2 smd: 2(-6.75,6.65) 3(-5.25,6.65) 4(-3.75,6.65) 5(-2.25,6.65) 6(-0.75,6.65) 7(0.75,6.65) 8(2.25,6.65) 9(3.75,6.65) 10(5.25,6.65) 11(6.75,6.65) 21(6.75,-6.65) 22(5.25,-6.65) 23(3.75,-6.65) 24(2.25,-6.65) 25(0.75,-6.65) 26(-0.75,-6.65) 27(-2.25,-6.65) 28(-3.75,-6.65) 29(-5.25,-6.65) 30(-6.75,-6.65)
  rect 2x1 smd: 13(8.9,4.5) 14(8.9,3) 15(8.9,1.5) 16(8.9,0) 17(8.9,-1.5) 18(8.9,-3) 19(8.9,-4.5) 32(-8.9,-4.5) 33(-8.9,-3) 34(-8.9,-1.5) 35(-8.9,0) 36(-8.9,1.5) 37(-8.9,3)
  rect 2x1 smd mask+0.102: 38(-8.9,4.5)
  silkscreen extent -10.15,-7.9 10.15,8.9, body extent -9.25,-7 9.25,7, height 1.9
MH_300_275_NPTH [mm] "Non-plated mount hole M2.5 3.00mm diameter"
  round 2.75 hole 2.75 unplated mask+0.25: 1(0,0)
  Keep-Out Layer circle w0.2: c0,0 r1.65
QPC02SXGN-RC [mm]
  body extent -2.49,-1.23 2.49,1.23, height 8.46
RESC1005X04N [mm] "Chip Resistor, 2-Leads, Body 1.00x0.50mm, IPC Medium Density"
  rect 0.66x0.62 smd: 1(-0.44,0) 2(0.44,0)
  body extent -0.53,-0.28 0.53,0.28, height 0.4
RESC1608X06L [mm] "Chip Resistor, 2-Leads, Body 1.55x0.80mm, IPC High Density"
  rrect50% 0.75x0.85 smd: 1(-0.65,0) 2(0.65,0)
  body extent -0.8,-0.45 0.8,0.45, height 0.55
RESC1608X06N [mm] "Chip Resistor, 2-Leads, Body 1.55x0.80mm, IPC Medium Density"
  rect 0.95x0.95 smd: 1(-0.75,0) 2(0.75,0)
  body extent -0.8,-0.45 0.8,0.45, height 0.55
RESC1608X06N_DNF [mm] "Chip Resistor, 2-Leads, Body 1.55x0.80mm, IPC Medium Density"
  rect 0.95x0.95 smd: 1(-0.75,0) 2(0.75,0)
  body extent -0.8,-0.45 0.8,0.45, height 0.55
SM2924-Footprint-1 [mm] "Footprint and 3D model for SM2924 component"
  rect 3.12x1 smd: 1(7.29,0)
  rect 2.54x2.47 smd: 2(7.001,-3.238) 2(7.001,3.239)
  Top Layer region: 7.255,2.404 7.255,2.2 8.718,2.2 8.718,2.404
  Top Layer region: 7.763,3.492 8.271,3.492 8.271,4.956 7.763,4.956
  Top Layer region: 8.718,2.912 8.718,3.42 7.255,3.42 7.255,2.912
  Top Layer region: 6.747,3.492 7.255,3.492 7.255,4.956 6.747,4.956
  Top Layer region: 8.718,3.928 8.718,4.436 7.255,4.436 7.255,3.928
  Top Layer region: 7.255,-3.928 7.255,-4.436 8.718,-4.436 8.718,-3.928
  Top Layer region: 6.747,-4.956 7.255,-4.956 7.255,-3.492 6.747,-3.492
  Top Layer region: 7.255,-2.912 7.255,-3.42 8.718,-3.42 8.718,-2.912
  Top Layer region: 7.763,-4.956 8.271,-4.956 8.271,-3.492 7.763,-3.492
  Top Layer region: 8.718,-2.404 8.718,-2.2 7.255,-2.2 7.255,-2.404
  Top Layer region: 5.791,5.235 5.791,4.727 7.254,4.727 7.254,5.235
  Top Layer region: 4.595,5.256 5.103,5.256 5.103,6.719 4.595,6.719
  Top Layer region: 5.611,5.256 6.119,5.256 6.119,6.719 5.611,6.719
  Top Layer region: 3.579,5.256 4.087,5.256 4.087,6.719 3.579,6.719
  Top Layer region: 2.563,5.256 3.071,5.256 3.071,6.719 2.563,6.719
  Top Layer region: 1.547,5.256 2.055,5.256 2.055,6.719 1.547,6.719
  Top Layer region: 0.531,5.256 1.039,5.256 1.039,6.719 0.531,6.719
  Top Layer region: -0.485,5.256 0.023,5.256 0.023,6.719 -0.485,6.719
  Top Layer region: -0.485,-6.719 0.023,-6.719 0.023,-5.256 -0.485,-5.256
  Top Layer region: 0.531,-6.719 1.039,-6.719 1.039,-5.256 0.531,-5.256
  Top Layer region: 1.547,-6.719 2.055,-6.719 2.055,-5.256 1.547,-5.256
  Top Layer region: 2.563,-6.719 3.071,-6.719 3.071,-5.256 2.563,-5.256
  Top Layer region: 3.579,-6.719 4.087,-6.719 4.087,-5.256 3.579,-5.256
  Top Layer region: 5.611,-6.719 6.119,-6.719 6.119,-5.256 5.611,-5.256
  Top Layer region: 4.595,-6.719 5.103,-6.719 5.103,-5.256 4.595,-5.256
  Top Layer region: 7.254,-5.236 7.254,-4.728 5.791,-4.728 5.791,-5.236
  Top Layer pour cut-out: 5.731,-0.627 5.73,-0.628 5.73,-2 8.977,-2 8.977,-0.63 8.977,-0.627
  Top Layer pour cut-out: 5.731,2.004 5.73,2.003 5.73,0.627 8.977,0.627 8.977,2 8.977,2 8.977,2.004
  Top Layer pour cut-out: -1.131,6.25 6.604,6.25 6.604,4.727 8.525,4.727 8.525,2 -1.131,2
  Top Layer pour cut-out: -1.131,-6.25 6.604,-6.25 6.604,-4.727 8.525,-4.727 8.525,-2 -1.131,-2
  Top Layer region: -0.75,-3.946 4.056,-3.946 4.117,-4.053 4.281,-4.238 4.49,-4.369 4.727,-4.437 4.973,-4.437 5.21,-4.369 5.419,-4.238 5.583,-4.053 5.644,-3.946 5.644,-3.946 6.35,-3.946 6.35,-5.996 -0.75,-5.996
  Top Layer region: -0.75,3.946 4.056,3.946 4.117,4.053 4.281,4.238 4.49,4.369 4.727,4.437 4.973,4.437 5.21,4.369 5.419,4.238 5.583,4.053 5.644,3.946 5.644,3.946 6.35,3.946 6.35,5.996 -0.75,5.996
  Top Layer keep-out lines w0: 5.73,2 8.977,2 8.977,0.627 5.73,0.627 5.73,2 ; 5.73,-0.627 5.73,-2 8.977,-2 8.977,-0.627 5.73,-0.627
  Keep-Out Layer board cut-out: -1.9,-3.565 -1.9,3.565 4.35,3.565 4.35,3.664 4.426,3.848 4.567,3.989 4.751,4.065 4.949,4.065 5.133,3.989 5.274,3.848 5.35,3.664 5.35,3.565 5.35,-3.565 5.35,-3.664 5.274,-3.848 5.133,-3.989 4.949,-4.065 4.751,-4.065 4.567,-3.989 4.426,-3.848 4.35,-3.664 4.35,-3.565
  Keep-Out Layer lines w0.013: -1.131,3.565 4.35,3.565 cw(c4.85,3.565) 5.35,3.565 5.35,-3.565 cw(c4.85,-3.565) 4.35,-3.565 -1.131,-3.565
  silkscreen extent 6.45,-5 7.35,5, body extent -7.45,-5.17 7.25,5.18, height 4.42
SOT-23 [mm]
  rect 0.9x0.95 smd: 1(-0.95,-1.175) 2(0.95,-1.175) 3(0,1.175)
  silkscreen extent -1.51,-0.68 1.41,0.72, body extent -1.52,-1.3 1.43,1.32, height 1
SOT-23_5 [mil]
  rect 39x25 smd: 1(-50,37.5) 2(-50,0) 3(-50,-37.5) 4(50,-37.5) 5(50,37.5)
  silkscreen extent -20,-60 20,60, body extent -52,-60 51,60, height 39
TP-100_BLACK [mm]
  rect 1.7x1.7 hole 1.3: 1(0,0)
  body extent -1.25,-1.25 1.25,1.25, height 4.5
U_FL-R-SMT [mm]
  rrect50% 1x1 smd: 1(0,-1.5)
  rect 1.05x2.2 smd: 2(-1.475,0) 3(1.475,0)
  Top Layer pour cut-out: 1.5,1.55 1.5,-1.55 -1.5,-1.55 -1.5,1.55
  Top Layer keep-out region: -1.5,-1.55 1.5,-1.55 1.5,1.55 -1.5,1.55
  silkscreen extent -1.55,-1.52 1.55,1.5, body extent -1.5,-1.55 1.5,1.55, height 1.25
USB-C_RCP [mm] "CONN RCP USB3.1 TYPEC 24P SMD RA"
  rect 0.28x0.7 smd mask+0.051: A1(-3,3.085) A2(-2.5,3.085) A3(-2,3.085) A4(-1.5,3.085) A5(-1,3.085) A6(-0.5,3.085) A7(0.5,3.085) A8(1,3.085) A9(1.5,3.085) A10(2,3.085) A11(2.5,3.085) A12(3,3.085) B2(2.25,1.385) B3(1.75,1.385) B4(1.25,1.385) B5(0.75,1.385) B6(0.25,1.385) B7(-0.25,1.385) B8(-0.75,1.385) B9(-1.25,1.385) B10(-1.75,1.385) B11(-2.25,1.385)
  rect 0.88x0.7 smd mask+0.051: B1(3.05,1.385) B12(-3.05,1.385)
  oval 1.1x2.1 hole 0.6 slot 1.6 at 90 deg: SH1(-4.32,2.275) SH2(4.32,2.275)
  oval 1.1x3.6 hole 0.6 slot 2.1 at 90 deg copper offset 0,0.5: SH3(4.62,-3.085) SH4(-4.62,-3.085)
  silkscreen extent -3.76,3.65 -3.51,3.9, body extent -4.7,-5.04 4.69,3.26, height 3.7

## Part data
C1 C2 C4 C6: library part CAP0084, "Cap,100nF,10V,+/-10%,X7R,0402", Component Rating=X7R, Manufacturer 1=Kemet, Manufacturer Part Number 1=C0402C104K8RACTU, Package=0402, Supplier Part Number 1=399-3520-2-ND, Tolerance=10%, Voltage=10V
C3 C5 C8 C9 C10 C11 C16: library part CAP0164, "CAP CER 10UF 25V 20% X5R 0603", Component Rating=X5R, Manufacturer 1="Murata, Inc.", Manufacturer Part Number 1=GRM188R61E106MA73J, Package=0603, Supplier Part Number 1=490-12737-2-ND, Tolerance=20%, Voltage=25V
C7: library part CAP0086, "CAP CER 2.2UF 6.3V 20% X5R 0402", Component Rating=X5R, Manufacturer 1="Taiyo Yuden", Manufacturer Part Number 1=JMK105BJ225MV-F, Package=0402, Supplier Part Number 1=587-1453-2-ND, Tolerance=20%, Voltage=6.3V
D1 D2: library part DIO0046, "LED GREEN 0402 SMD", Manufacturer 1=SunLED, Manufacturer Part Number 1=XZVGR68W-3, Package=0402, Supplier Part Number 1=1497-1386-2-ND, Voltage=2.0V
FID1 FID2 FID3: library part PAD0013, "1mm Round Fiducial, 0.5mm Space"
H1: library part HDR0098, "Conn Straight Header 2x1 0.100\" 2 POS (DNF)", Manufacturer 1=DNF, Package=THRU-Hole
H2: library part HDR0169, "CONN HEADER VERT 3POS 1.27MM", Manufacturer 1="Adam Tech", Manufacturer Part Number 1=HPH1-A-03-UA, Package=THRU_Hole, Supplier Part Number 1=2057-HPH1-A-03-UA-ND
H3: library part HDR0143, "CONN,Vertical FTSH Series,0.05\"16 Pins, Through Hole", Manufacturer 1=Samtec, Manufacturer Part Number 1=FTSH-108-01-F-D-K, Package="FTSH 108D"
H4: library part HDR0151, "Conn Female Header 20x2 0.100\" 40 POS", Manufacturer 1="Sullins Electronics, Corp", Manufacturer Part Number 1=PPPC202LFBN-RC, Package=THRU-Hole, Supplier Part Number 1=S7123-ND
H5: library part CON0012, "U.FL RF Connector", Manufacturer 1=Hirose, Manufacturer Part Number 1=U.FL-R-SMT, Package=SMT, Supplier Part Number 1=H9161TR-ND
H6: library part HDR0006, "Conn Straight Header 2x1 0.100\" 2 POS", Manufacturer 1=Oupiin, Manufacturer Part Number 1=2011-1X02G00SB-1, Package=THRU-Hole, Supplier Part Number 1=2553-2011-1X02G00SB-1-ND
H7: library part JCK0138-4, "Wanshih RF SMD SMA connector with 2 GND pillars - Smaller Connector Barrel"
J1: library part CON0045, Manufacturer 1=Molex, Manufacturer Part Number 1=2012670005, Supplier Part Number 1=WM17992TR-ND
J2: library part HDR0012, "Conn Straight Header 5x2 0.100\" 10 POS", Manufacturer 1="Molex/Waldom Electronics Corp", Manufacturer Part Number 1=90131-0125, Package=THRU-Hole, Supplier Part Number 1=WM8123-ND
J3 J4 J5: library part HDR0170, "CONN JUMPER SHORTING .100\" GOLD", Manufacturer 1="Sullins Connector Solutions", Package=Jumper_Header, Supplier Part Number 1=S9337-ND
L1: library part IND0083, "BEAD 60OHMS 2500MA 32 MOHM", Current=2.5A, Manufacturer 1=Murata, Manufacturer Part Number 1=BLM15PX600SN1D, Package=0402, Resistance=32mOhm, Supplier Part Number 1=490-11023-1-ND
MH1 MH2 MH3 MH4: library part PAD0031, "MH NPTH 3.00mm DIA 2.75mm HOLE"
Q1: library part TSR0024, "MOSFET N-CH 50V 220MA SOT23-3", Manufacturer 1=onsemi, Manufacturer Part Number 1=BSS138K, Package=SOT-23-3, Supplier Part Number 1=BSS138KCT-ND, Voltage=50V
R1: library part RES0004, "RES SMD 1Kohm 1% 1/10W Thick film 0402", Manufacturer 1=Panasonic, Manufacturer Part Number 1=ERJ-2RKF1001X, Package=0402, Power=1/10W, Supplier Part Number 1=P1.00KLCT-ND, Tolerance=1%
R2 R3: library part RES0204, "RES SMD 3.9K OHM 1% 1/16W 0402", Manufacturer 1=Yageo, Manufacturer Part Number 1=RC0402FR-073K9L, Package=0402, Power=1/16W, Supplier Part Number 1=311-3.90KLRCT-ND, Tolerance=1%
R4 R5 R6 R7 R8 R9 R10 R11 R12 R13 R14 R15 R16 R18 R20 R24: library part RES0002, "RES SMD 10Kohm 1% 1/10W Thick film 0402", Manufacturer 1=Panasonic, Manufacturer Part Number 1=ERJ-2RKF1002X, Package=0402, Power=1/10W, Supplier Part Number 1=P10.0KLCT-ND, Tolerance=1%
R17 R19 R21 R22 R23 R25: library part RES0086, "Res, 47K Ohms,1/16W, 1%, 0402,SMD RoHS", Manufacturer 1=Rohm, Manufacturer 2=Yageo, Manufacturer Part Number 1=MCR01MZPF4702, Manufacturer Part Number 2=RC0402FR-0747KL, Package=0402, Power=1/16W, Supplier Part Number 1=311-47.0KLRCT-ND, Tolerance=1%
R26 R27 R28 R29 R30 R42 R43 R44 R45 R46 R49 R55 R56 R57 R58 R63: library part RES0119, "Res, 0 Ohm, 1/10W,+/-5%,0603 RoHS", Manufacturer 1=Rohm, Manufacturer 2=Yageo, Manufacturer Part Number 1=MCR03EZPJ000, Manufacturer Part Number 2=RC0603JR-070RL, Package=0603, Power=1/10W, Supplier Part Number 1=311-0.0GRCT-ND, Tolerance=5%
R31: library part RES0284, "RES 82K OHM 1% 1/16W 0402", Manufacturer 1=Yageo, Manufacturer Part Number 1=RC0402FR-0782KL, Package=0402, Power=1/16W, Tolerance=1%
R32 R34 R36 R40: library part RES0035, "Update Later", Package=0603, Power=DNF
R33 R35 R37 R38 R39 R41: library part RES0282, "RES SMD 47 OHM 5% 1/10W 0603", Manufacturer 1="Panasonic Electronic Components", Manufacturer Part Number 1=ERJ-3GEYJ470V, Package=0603, Power=1/10W, Supplier Part Number 1=P47GTR-ND, Tolerance=5%
R47: library part RES0044, "Res,100K Ohms,1/16W, 1%, 0402,SMD RoHS", Manufacturer 1=Rohm, Manufacturer 2=Yageo, Manufacturer Part Number 1=MCR01MZPF1003, Manufacturer Part Number 2=RC0402FR-07100KL, Package=0402, Power=1/16W, Supplier Part Number 1=311-100KLRCT-ND, Tolerance=1%
R48: library part RES0124, "Res, 10K Ohm, 1/10W,+/-1%,0603 RoHS", Manufacturer 1=Rohm, Manufacturer 2=Yageo, Manufacturer Part Number 1=MCR03EZPFX1002, Manufacturer Part Number 2=RC0603FR-0710KL, Package=0603, Power=1/10W, Supplier Part Number 1=311-10.0KHRCT-ND, Tolerance=1%
R50: library part RES0011, "RES SMD 18.7K 1% 1/10W Thick film 0402", Manufacturer 1=Panasonic, Manufacturer Part Number 1=ERJ-2RKF1872X, Package=0402, Power=1/10W, Supplier Part Number 1=P18.7KLCT-ND, Tolerance=1%
R51 R64: library part RES0244, "RES SMD 10K OHM 0.1% 1/16W 0402", Manufacturer 1=YAGEO, Manufacturer Part Number 1=RT0402BRD0710KL, Package=0402, Power=1/16W, Supplier Part Number 1=YAG1346CT-ND, Tolerance=0.1%
R52: library part RES0285, "RES 7.32K OHM 1% 1/16W 0402", Manufacturer 1=Yageo, Manufacturer Part Number 1=RC0402FR-077K32L, Package=0402, Power=1/16W, Tolerance=5%
R59 R60: library part RES0094, "Res, 5.1K Ohms, 1/16W, 1%, 0402,SMD", Manufacturer 1=Rohm, Manufacturer 2=Yageo, Manufacturer Part Number 1=MCR01MZPF5101, Manufacturer Part Number 2=RC0402FR-075K1L, Package=0402, Power=1/16W, Supplier Part Number 1=311-5.10KLRCT-ND, Tolerance=1%
R61 R62: library part RES0073, "Res, 330 Ohms, 1/16W, 1%, 0402,SMD", Manufacturer 1=Rohm, Manufacturer 2=Yageo, Manufacturer Part Number 1=MCR01MZPF3300, Manufacturer Part Number 2=RC0402FR-07330RL, Package=0402, Power=1/16W, Supplier Part Number 1=311-330LRCT-ND, Tolerance=1%
R65: library part RES0281, "Ohms Jumper Chip Resistor 0603 ( 1608 Metric) - RES_AB", Manufacturer 1=Rohm, Manufacturer 2=Yageo, Manufacturer Part Number 1=MCR03EZPJ000, Manufacturer Part Number 2=RC0603JR-070RL, Package=0603, Power=1/10W, Supplier Part Number 1=311-0.0GRCT-ND, Tolerance=5%
R72: library part RES0240, "RES 1K OHM 0.5% 1/16W 0402", Manufacturer 1=YAGEO, Manufacturer Part Number 1=RC0402DR-071KL, Package=0402, Power=1/16W, Supplier Part Number 1=13-RC0402DR-071KLCT-ND, Tolerance=0.5%
TP1 TP6 TP7: library part CON0001, "Test Point PCB, BLACK 0.040\"D", Manufacturer 1="Keystone Electronics", Manufacturer Part Number 1=5001, Package=THRU-Hole, Supplier Part Number 1=5001K-ND
U1: library part ICT0220, "IC EEPROM 32KBIT I2C 1MHZ 8UDFN", Manufacturer 1=OnSemi, Package=UDFN8, Supplier Part Number 1=CAT24C32HU4I-GT3OSCT-ND
U2: library part MOD0018, "MM61xx-MF08", Manufacturer 1="Morse Micro", Manufacturer Part Number 1=MM61xx-MF08251
U3: library part REG0071, "IC REG LIN 3.3V 600MA TSOT23-5", Current=600mA, Manufacturer 1="Richtek USA Inc.", Manufacturer Part Number 1=RT9080-33GJ5, Package=SOT23-5, Supplier Part Number 1=1028-1509-2-ND, Voltage=3.3V
U4: library part REG0079, "IC REG LDO ADJ 0.6A SOT23-5", Current=600mA, Manufacturer 1="Richtek USA Inc.", Manufacturer Part Number 1=RT9187CGB, Package=SOT23-5, Supplier Part Number 1=1028-1226-2-ND, Voltage=ADJ
VS1: library part DIO0056, "TVS DIODE 6V 10.3V DO214AC", Current=38.8A, Manufacturer 1="Littelfuse Inc.", Manufacturer Part Number 1=SMAJ6.0A, Package=DO-214AC, Supplier Part Number 1=SMAJ6.0ALFCT-ND, Voltage=6V

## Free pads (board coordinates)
  oval 1.524x1.016 hole 0.711: 2(23.691,35.502) 3(23.691,33.978) 4(23.691,29.533) 7(23.691,32.454) 9(23.691,31.057) 10(23.691,28.009) 11(23.691,26.485) 12(23.691,24.961) 19(41.341,22.04) 20(41.341,23.564) 21(41.341,24.961) 22(41.341,26.485) 24(41.341,31.057) 25(41.341,34.013) 27(41.341,32.539) 31(41.341,35.502)
  oval 1.016x1.524 hole 0.711: 14(30.976,17.803) 15(32.5,17.803) 16(34.024,17.803) 17(35.548,17.803) 29(32.5,39.739) 30(34.024,39.739) 34(30.976,39.739) 35(35.473,39.739)

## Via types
v1: diameter 0.6, hole 0.3, Top Layer to Bottom Layer, tented both sides, 608 vias

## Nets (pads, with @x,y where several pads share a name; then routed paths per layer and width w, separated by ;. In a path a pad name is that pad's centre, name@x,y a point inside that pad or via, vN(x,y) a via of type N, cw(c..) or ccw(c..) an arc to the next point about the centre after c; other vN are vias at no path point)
5V_USB: C16.1 J1.A4 J1.A9 J1.B4 J1.B9 R55.2 R56.1 VS1.K | length 23.3
  Top Layer w0.254: v1(5.818,37.79) 5.823,37.785 6.624,37.785 J1.B4@6.629,37.78 7.181,37.78 7.433,38.032 v1(7.527,38.032) ; v1(5.83,40.259) 5.841,40.27 6.618,40.27 J1.B9@6.629,40.28 6.642,40.267 7.124,40.267 7.426,39.965 v1(7.493,39.965) ; v1(7.493,37.146) 7.864,37.517 8.316,37.517 8.317,37.518 8.319,37.516 8.992,37.516 v1(8.994,37.514) ; v1(7.493,40.88) 7.56,40.88 7.896,40.543 8.316,40.543 J1.A4@8.329,40.53 8.342,40.543 8.79,40.543 9.05,40.803 v1(9.144,40.803)
  Top Layer w0.508: v1(10.688,39.878) VS1.K@11.545,39.878 ; v1(10.688,40.513) 11.545,40.513 VS1.K@11.926,40.513 ; v1(10.688,41.148) VS1.K@11.926,41.148 ; v1(11.545,39.243) VS1.K@11.545,39.878 ; VS1.K@11.545,40.481 VS1.K@11.545,39.878 ; VS1.K@11.926,39.878 VS1.K@11.545,39.878 ; v1(12.18,39.243) 12.18,39.878 VS1.K@12.18,40.481 ; VS1.K@12.434,39.878 VS1.K@12.815,39.878 ; VS1.K@12.434,40.513 12.815,40.513 v1(13.672,40.513) ; VS1.K@12.434,41.148 v1(13.672,41.148) ; v1(12.815,39.243) VS1.K@12.815,39.878 ; VS1.K@12.815,40.481 VS1.K@12.815,39.878 ; v1(13.672,39.878) VS1.K@12.815,39.878
  Top Layer w0.635: VS1.K@12.18,41.032 12.18,42.313 14.593,42.313 R56.1@15.825,42.313
CC1: J1.A5 R59.1 | length 3.7
  Top Layer w0.203: J1.A5@8.329,40.03 8.98,40.03 9.411,40.03 10.021,40.64 10.021,41.716 R59.1@10.021,42.351
CC2: J1.B5 R60.1 | length 4
  Top Layer w0.203: J1.B5@6.632,38.284 6.667,38.319 7.029,38.319 7.7,38.989 8.954,38.989 9.894,38.049 R60.1@9.894,38.024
